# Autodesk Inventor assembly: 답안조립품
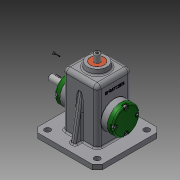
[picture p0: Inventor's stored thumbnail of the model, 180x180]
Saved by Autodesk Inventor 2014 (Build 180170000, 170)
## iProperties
Created: 2016-02
Part Number: 답안조립품
Document SubType Name: Assembly
Designer: Administrator
Author: Administrator
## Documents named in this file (16)
- C:\Users\Administrator\Desktop\460211V1037\답안조립품.iam
- C:\Users\Administrator\Desktop\460211V1037\1-몸체.ipt
- C:\Users\Administrator\Desktop\460211V1037\V벨트풀리.ipt
- C:\Users\Administrator\Desktop\460211V1037\고정핀 1.2 x 10.ipt
- C:\Users\Administrator\Desktop\460211V1037\뒤커버.ipt
- C:\Users\Administrator\Desktop\460211V1037\링크.ipt
- C:\Users\Administrator\Desktop\460211V1037\멈춤나사 M3x8.ipt
- C:\Users\Administrator\Desktop\460211V1037\베어링 12 x 32 x 10.ipt
- C:\Users\Administrator\Desktop\460211V1037\볼트 M4 x 12.ipt
- C:\Users\Administrator\Desktop\460211V1037\부시.ipt
- C:\Users\Administrator\Desktop\460211V1037\슬라이드.ipt
- C:\Users\Administrator\Desktop\460211V1037\앞커버.ipt
- C:\Users\Administrator\Desktop\460211V1037\오일실 12 25 7.ipt
- C:\Users\Administrator\Desktop\460211V1037\키 4 x 4 x 10.ipt
- C:\Users\Administrator\Desktop\460211V1037\편심축.ipt
- C:\Users\Administrator\Desktop\460211V1037\핀 5 x 18.ipt
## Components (12 placed, 5 different names)
1. 1-몸체:1
2. V벨트풀리:1
3. 고정핀 1.2 x 10:1
4. 핀 5 x 18:1
5. ISO 4762 M4 x 12:1
6. ISO 4762 M4 x 12:3
7. ISO 4762 M4 x 12:4
8. ISO 4762 M4 x 12:5
9. ISO 4762 M4 x 12:2
10. ISO 4762 M4 x 12:6
11. ISO 4762 M4 x 12:7
12. ISO 4762 M4 x 12:8
